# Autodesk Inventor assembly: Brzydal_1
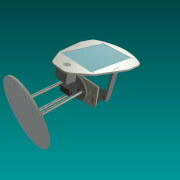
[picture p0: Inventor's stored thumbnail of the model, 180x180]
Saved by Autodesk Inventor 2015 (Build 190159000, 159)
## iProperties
Created: 2016-02
Part Number: Brzydal_1
Document SubType Name: Assembly
Designer: Rafał
Author: Rafał
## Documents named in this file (12)
- C:\Users\Rafał\Dropbox\Brzydal\Mechanika\Brzydal_1.iam
- C:\Users\Rafał\Dropbox\Brzydal\Mechanika\MG996R.ipt
- C:\Users\Rafał\Dropbox\Brzydal\Mechanika\orczyk_okragly.ipt
- C:\Users\Rafał\Dropbox\Brzydal\Mechanika\sruba_2_5.ipt
- C:\Users\Rafał\Dropbox\Brzydal\Mechanika\talerz.ipt
- C:\Users\Rafał\Dropbox\Brzydal\Mechanika\mocowanie_twarzy.ipt
- C:\Users\Rafał\Dropbox\Brzydal\Mechanika\twarz.ipt
- C:\Users\Rafał\Dropbox\Brzydal\Mechanika\podstawka dolna.ipt
- C:\Users\Rafał\Dropbox\Brzydal\Mechanika\sruba_80.ipt
- C:\Users\Rafał\Dropbox\Brzydal\Mechanika\twarz_ekran.ipt
- C:\Users\Rafał\Dropbox\Brzydal\Mechanika\sam_dol.ipt
- C:\Users\Rafał\Dropbox\Brzydal\Mechanika\kamera.ipt
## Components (29 placed, 11 different names)
1. MG996R:1 — Insert:5, Mate:21, Mate:22, Mate:23
2. orczyk_okragly:1 — Insert:5, Insert:6, Insert:7, Insert:8, Insert:9, Rotational:3
3. sruba_2_5:1 — Insert:8
4. sruba_2_5:2 — Insert:9
5. sruba_2_5:3 — Insert:7
6. sruba_2_5:4 — Insert:6
7. MG996R:2 — Insert:11, Mate:24, Mate:25, Mate:26
8. MG996R:3 — Insert:10, Mate:27, Mate:28, Mate:29
9. orczyk_okragly:2 — Insert:10, Insert:14, Insert:15, Insert:16, Insert:17, Rotational:1
10. orczyk_okragly:3 — Insert:11, Insert:12, Insert:13, Insert:18, Insert:19, Rotational:2
11. sruba_2_5:5 — Insert:15
12. sruba_2_5:6 — Insert:12
13. sruba_2_5:7 — Insert:14
14. sruba_2_5:8 — Insert:13
15. sruba_2_5:9 — Insert:17
16. sruba_2_5:10 — Insert:18
17. sruba_2_5:11 — Insert:19
18. sruba_2_5:12 — Insert:16
19. mocowanie_twarzy:1 — Rotational:2, Mate:19, Mate:20, Flush:3
20. mocowanie_twarzy:2 — Rotational:1, Flush:4
21. twarz:1 — Mate:19, Mate:20, Flush:3, Flush:4, Mate:30, Mate:31, Flush:5, Rotational:4
22. talerz:1 — Rotational:3, Mate:24, Mate:25, Mate:26, Mate:27, Mate:28, Mate:29
23. podstawka dolna:1 — Mate:21, Mate:22, Mate:23, Insert:20, Insert:21, Insert:22
24. sruba_80:1 — Insert:21
25. sruba_80:2 — Insert:20, Insert:23
26. sruba_80:3 — Insert:22
27. twarz_ekran:1 — Mate:30, Mate:31, Flush:5
28. sam_dol:1 — Insert:23
29. kamera:1 — Rotational:4
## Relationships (39: Insert 19, Mate 13, RevoluteJoint 4, Flush 3)
- Insert:5: MG996R:1 ↔ orczyk_okragly:1
- Insert:6: orczyk_okragly:1 ↔ sruba_2_5:4
- Insert:7: orczyk_okragly:1 ↔ sruba_2_5:3
- Insert:8: orczyk_okragly:1 ↔ sruba_2_5:1
- Insert:9: orczyk_okragly:1 ↔ sruba_2_5:2
- Insert:10: MG996R:3 ↔ orczyk_okragly:2
- Insert:11: MG996R:2 ↔ orczyk_okragly:3
- Insert:12: orczyk_okragly:3 ↔ sruba_2_5:6
- Insert:13: orczyk_okragly:3 ↔ sruba_2_5:8
- Insert:14: orczyk_okragly:2 ↔ sruba_2_5:7
- Insert:15: orczyk_okragly:2 ↔ sruba_2_5:5
- Insert:16: orczyk_okragly:2 ↔ sruba_2_5:12
- Insert:17: orczyk_okragly:2 ↔ sruba_2_5:9
- Insert:18: orczyk_okragly:3 ↔ sruba_2_5:10
- Insert:19: orczyk_okragly:3 ↔ sruba_2_5:11
- Rotational:1 [RevoluteJoint]: orczyk_okragly:2 ↔ mocowanie_twarzy:2
- Rotational:2 [RevoluteJoint]: orczyk_okragly:3 ↔ mocowanie_twarzy:1
- Mate:19: mocowanie_twarzy:1 ↔ twarz:1
- Mate:20: mocowanie_twarzy:1 ↔ twarz:1
- Flush:3: mocowanie_twarzy:1 ↔ twarz:1
- Flush:4: mocowanie_twarzy:2 ↔ twarz:1
- Mate:21: MG996R:1 ↔ podstawka dolna:1
- Mate:22: MG996R:1 ↔ podstawka dolna:1
- Mate:23: MG996R:1 ↔ podstawka dolna:1
- Rotational:3 [RevoluteJoint]: orczyk_okragly:1 ↔ talerz:1
- Mate:24: MG996R:2 ↔ talerz:1
- Mate:25: MG996R:2 ↔ talerz:1
- Mate:26: MG996R:2 ↔ talerz:1
- Mate:27: MG996R:3 ↔ talerz:1
- Mate:28: MG996R:3 ↔ talerz:1
- Mate:29: MG996R:3 ↔ talerz:1
- Insert:20: podstawka dolna:1 ↔ sruba_80:2
- Insert:21: podstawka dolna:1 ↔ sruba_80:1
- Insert:22: podstawka dolna:1 ↔ sruba_80:3
- Mate:30: twarz:1 ↔ twarz_ekran:1
- Mate:31: twarz:1 ↔ twarz_ekran:1
- Flush:5: twarz:1 ↔ twarz_ekran:1
- Insert:23: sruba_80:2 ↔ sam_dol:1
- Rotational:4 [RevoluteJoint]: twarz:1 ↔ kamera:1
